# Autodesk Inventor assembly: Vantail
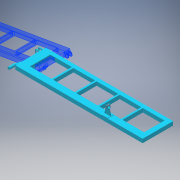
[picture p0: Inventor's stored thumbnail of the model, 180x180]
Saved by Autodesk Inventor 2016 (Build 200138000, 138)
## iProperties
Shininess: 64.0
Length Units: 11269
Angle Units: 11279
Time Units: 11290
Mass Units: 11283
Length Display Precision: 3
Angle Display Precision: 2
Compacted: True
Created: 2007-01
Part Number: Vantail
Document SubType Name: Assembly
Designer: plantier
Mass: 3192.19 g
Surface Area: 4056.58 cm^2
Volume: 3192.19 cm^3
Density: 1 g/cm^3
Density: 0.0
Volumn: 0.0
Area: 0.0
PropertySet Name: Model Information
Control State: 0
Master: False
Checked Out: False
Author: plantier
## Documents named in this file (5)
- D:\Cours\1-Cours-2016-17\1Ssi\5. Statique\FAAC\Portail\Vantail 1metre.iam
- D:\Cours\1-Cours-2016-17\1Ssi\5. Statique\FAAC\Portail\Chape vantail.ipt
- D:\Cours\1-Cours-2016-17\1Ssi\5. Statique\FAAC\Portail\Axe.ipt
- D:\Cours\1-Cours-2016-17\1Ssi\5. Statique\FAAC\Portail\Circlips.ipt
- D:\Cours\1-Cours-2016-17\1Ssi\5. Statique\FAAC\Portail\vantail 1metre.ipt
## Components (5 placed, 4 different names)
1. vantail 1metre:1 — Plaquage:1, Affleurement:1, Affleurement:2
2. Chape vantail:1 — Plaquage:1, Affleurement:1, Affleurement:2, Plaquage:2, Plaquage:7
3. Axe:1 — Plaquage:2, Plaquage:3, Plaquage:4, Plaquage:5, Plaquage:6
4. Circlips:1 — Plaquage:5, Plaquage:6, Plaquage:7
5. Circlips:2 — Plaquage:3, Plaquage:4
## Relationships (9: Mate 7, Flush 2)
- Plaquage:1 [Mate]: vantail 1metre:1 ↔ Chape vantail:1
- Affleurement:1 [Flush]: vantail 1metre:1 ↔ Chape vantail:1
- Affleurement:2 [Flush]: vantail 1metre:1 ↔ Chape vantail:1
- Plaquage:2 [Mate]: Chape vantail:1 ↔ Axe:1
- Plaquage:3 [Mate]: Axe:1 ↔ Circlips:2
- Plaquage:4 [Mate]: Axe:1 ↔ Circlips:2
- Plaquage:5 [Mate]: Axe:1 ↔ Circlips:1
- Plaquage:6 [Mate]: Axe:1 ↔ Circlips:1
- Plaquage:7 [Mate]: Chape vantail:1 ↔ Circlips:1
